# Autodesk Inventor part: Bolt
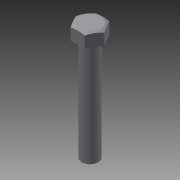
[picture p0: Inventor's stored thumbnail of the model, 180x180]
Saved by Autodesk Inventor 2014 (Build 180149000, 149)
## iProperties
Created: 2004-07
Part Number: Bolt
Document SubType Name: Modeling
Designer: Autodesk, Inc.
Manufacturer: Standard
Standards Organization: Custom
Density: 1 g/cm^3
Mass: 21.9731 g
Surface Area: 62.2533 cm^2
Volume: 21.9731 cm^3
Material: Generic
Appearance: Default
Author: Autodesk, Inc.
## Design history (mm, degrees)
sketch "Sketch1"
  geometry: L1 (-12.99, 0)-(-6.495, 11.25); L2 (-6.495, 11.25)-(6.495, 11.25); L3 (6.495, 11.25)-(12.99, 0); L4 (12.99, 0)-(6.495, -11.25); L5 (6.495, -11.25)-(-6.495, -11.25); L6 (-6.495, -11.25)-(-12.99, 0); 2 further points
  constraints: 12 end point, 1 coincident, 11 other
  dimensions: "Bolt_Width" = 22.5 distance between parallel lines of L5 L2 (= 1.5 x Bolt_Diameter)
extrude "Extrusion1" new body sketch "Sketch1" taper "d2" = 0 deg; distance "Bolt_Height" = 12
sketch "Sketch2"
  geometry: L1 (0, -2.6)-(0, 15.6) reference; L2 (13.8, 13)-(13.8, 10); L3 (13.8, 10)-(7.8, 13); L4 (7.8, 13)-(13.8, 13); L5 (12.99, 0)-(6.495, 0) reference; L6 (6.495, 0)-(-6.495, 0) reference; L7 (-6.495, 0)-(-12.99, 0) reference; L8 (-12.99, 0)-(-6.495, 0) reference; L9 (-6.495, 0)-(6.495, 0) reference; L10 (6.495, 0)-(12.99, 0) reference
  constraints: 6 end point, 1 parallel, 1 perpendicular
  dimensions: "d3" = 27.6 diameter of L2 L1; "d4" = 3 distance of L2.start L2.end; "d5" = 13 distance between parallel lines of L4 L5; "d6" = 6 distance of L3.end L2.start
revolve "Revolution1" sketch "Sketch2" stored, may be unused: angle "d7" = 90 deg
sketch "Sketch3"
  geometry: C1 r 7.5 at (0, 0); 1 further point
  constraints: 1 centre point, 1 coincident
  dimensions: "Bolt_Diameter" = 15 diameter of C1
extrude "Extrusion2" join sketch "Sketch3" taper "d10" = 0 deg; distance "Bolt_Length" = 95
body "Solid1"
node "Projected Loop1"
